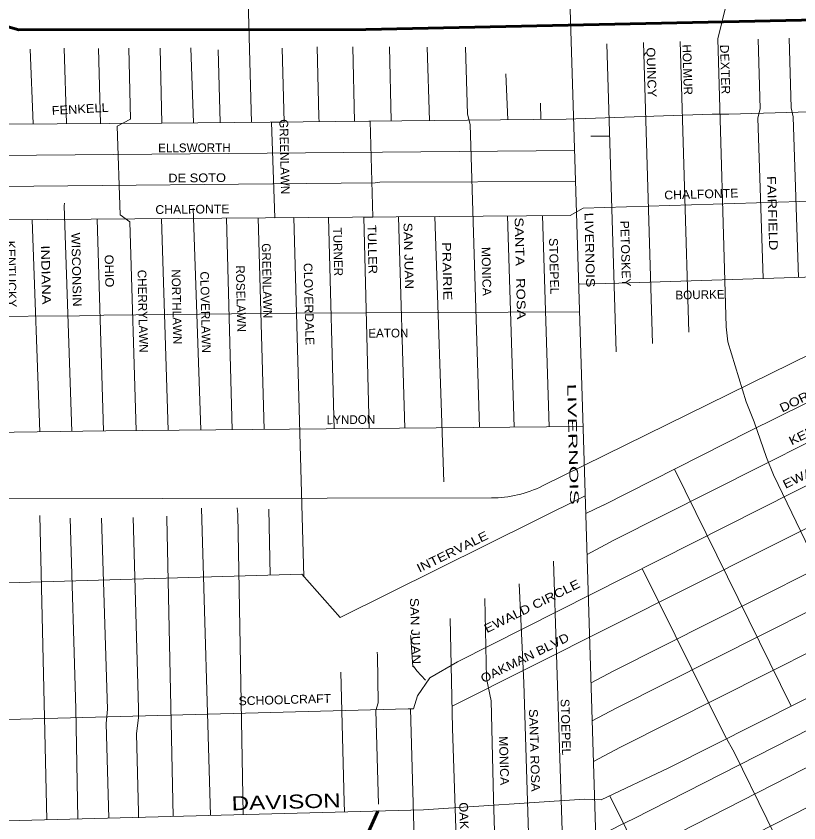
# Model space of a CAD drawing. Extents: x 34705 to 138605, y 34275 to 143551.
# Drawn here: x 69930 to 76666, y 119866 to 126812 of the extents above; entities that cross this region are included whole.
import ezdxf
from ezdxf.enums import TextEntityAlignment as Align

# ---------------------------------------------------------------- set-up
doc = ezdxf.new("R2010")
doc.units = 0
doc.header["$LTSCALE"] = 30
for name, color, linetype, lineweight in [('1', 7, 'Continuous', 13), ('11', 7, 'Continuous', 13), ('50', 7, 'Continuous', 13), ('51', 7, 'Continuous', 35)]:
    doc.layers.add(name, color=color, linetype=linetype, lineweight=lineweight)

msp = doc.modelspace()

# ---------------------------------------------------------------- linework, layer by layer
at = {"layer": '1'}
for p, q in [((76045.57, 126932.67), (75968.12, 126616.04)), ((75014.92, 126572.93), (75092.87, 123921.17)), ((75328.39, 126584.1), (75406.15, 123994.9)), ((75646.18, 126592.47), (75719.44, 124091.69)), ((70049.64, 126527.23), (70076.17, 125884.46)), ((70342.22, 126536.63), (70363.6, 125886.4)), ((70640.17, 126532.27), (70656.88, 125888.38)), ((71168.61, 126537.75), (71185.01, 125891.95)), ((71433.48, 126538.85), (71457.62, 125893.79)), ((71668.62, 126520.95), (71685.58, 125895.33)), ((73143.78, 126546.92), (73158.33, 125909.28)), ((73468.74, 126544.87), (73486.85, 125912.76)), ((74144.01, 126314.65), (74161.64, 125919.9)), ((74443.94, 126063.07), (74446.23, 125922.92)), ((72537.64, 125914.61), (72538.33, 125907.31)), ((74876.31, 125779.3), (75038.26, 125779.3)), ((69483.93, 125608.86), (74736.41, 125655.34)), ((71452.53, 125159.71), (71520, 123248.88)), ((70069.06, 125059.45), (70134, 123233.1)), ((70627.01, 125063.87), (70683.32, 123240.99)), ((71181.9, 125068.26), (71238.52, 123246.22)), ((71739.56, 125072.68), (71790.02, 123251.42)), ((72013.5, 125074.84), (72064.22, 123254)), ((72618.21, 125079.63), (72667.93, 123259.69)), ((73221.78, 125084.41), (73274.03, 123265.4)), ((73532.18, 125086.87), (73609.63, 122802.13)), ((74159.71, 125091.83), (74216.18, 123274.28)), ((74459.16, 125094.2), (74517.35, 123277.37)), ((75597.32, 122911.18), (76600.58, 120871.01)), ((71525.01, 122574.76), (71601.57, 119929.76)), ((72105.96, 122568.12), (72116.88, 121999.09)), ((74554.45, 122119.23), (74741.93, 116266.39)), ((73051.69, 119971.59), (73051.81, 119967.63))]:
    msp.add_line(p, q, dxfattribs=at)
for points in [[(74269.09, 141753.87), (74342.79, 139035.88), (74401.15, 136407.9), (74440.05, 135250.17), (74447.86, 135168.57), (74511.2, 133233.12), (74537.31, 132174.65), (74629.7, 129069.96), (74724.29, 126046.91), (75258.72, 108770.25), (75949.8, 107475.21), (75982.05, 107419.91), (76018.21, 107315.9)], [(71476.16, 141674.2), (71680.76, 133843.82), (71699.86, 133695.52), (71793.56, 131195.42), (71823.46, 129436.72), (71840.38, 128528.4), (71884.66, 128529.12), (71955.88, 125897.16)], [(75968.12, 126616.04), (76041.94, 124137.77), (76055.76, 124008.73), (76212.41, 123492.56), (76281.51, 123319.74), (76387.48, 123010.96), (76447.37, 122863.48), (76682.34, 122374.97), (76944.95, 121831.14), (78075.42, 119570.88)], [(76315.02, 126612.75), (76332.19, 126013.5), (76313.76, 125935.15), (76359.51, 124553.17)], [(76582.13, 126621.71), (76599.41, 126022.71), (76617.84, 125944.37), (76663.87, 124562.81)], [(70899.62, 126536.24), (70914.56, 125925.42), (70800.96, 125865.62), (70824.86, 125099.92), (70908.56, 125040.12), (70964.24, 123243.64)], [(72220.14, 126536.75), (72236.35, 125899.51), (72127.07, 125898.35), (72157.58, 125075.98), (72321.44, 125077.28), (72406.89, 121986.02)], [(72521.59, 126548.46), (72535.06, 125941.82), (72538.77, 125902.72)], [(72827.46, 126547.74), (72841, 125905.91), (72978.14, 125907.37), (73001.04, 125082.66), (72923.53, 125082.05), (72968.08, 123262.52)], [(73797.06, 126544.11), (73814.66, 125968.82), (73838.56, 125879.02), (73918.23, 123271.48)], [(71185.01, 125891.95), (72115.46, 125898.23), (74664.69, 125925.23), (75921.48, 125967.65), (76064.12, 125967.65), (76958.52, 125994.65), (77170.56, 126006.21), (78402.28, 126029.35), (80444.64, 126083.38)], [(82348.46, 126060.51), (80168.87, 124977.52), (78714.8, 124245.43), (77762.83, 122918.85), (73682.36, 120871.78)], [(69832.23, 125882.81), (71185.01, 125891.95)], [(69492.13, 125342.72), (73021.43, 125377.62), (73059.98, 125381.47), (74744.64, 125389.24)], [(55496.93, 125039.26), (55625.92, 124964.98), (55934.33, 124803.01), (56150.22, 124660.32), (56196.48, 124644.89), (58409.36, 124714.31), (60322.48, 124779.87), (61583.13, 124822.29), (61671.8, 124837.72), (64198.86, 124926.41), (64869.66, 124941.84), (66377.03, 124972.69), (66974.59, 124984.26), (69826.45, 125057.53), (74698.43, 125096.1), (74810.23, 125157.8), (77421.15, 125238.78)], [(70345.56, 125201.9), (70344.96, 125177.72), (70408.58, 123237)], [(74878.22, 121070.78), (75073.34, 121174.11), (78037.97, 122666.55), (79283.19, 123282.62), (80809.84, 124042.33), (82074.89, 124668.16)], [(74771.99, 124504.96), (75115.75, 124513.77), (77428.86, 124587.05)], [(74833.11, 122529.12), (74980.82, 122600.99), (74984.67, 122600.99), (76241.46, 123237.31), (78640.9, 124424.82)], [(74888.28, 120745.82), (75092.62, 120854.03), (78057.25, 122346.47), (78596.01, 122608.71), (82207.79, 124417.59)], [(68216.91, 124185.99), (68374.98, 124189.85), (68640.98, 124201.41), (68721.94, 124201.41), (69022.65, 124209.13), (69296.36, 124220.7), (69593.21, 124224.55), (70476.05, 124232.27), (70686.15, 124236.12), (72330.38, 124255.4), (74774.57, 124266.97)], [(74899.11, 120395.63), (75131.17, 120518.52), (78095.8, 122010.96), (79468.24, 122688.73), (81091.27, 123510.15), (81168.37, 123544.85), (81881.41, 123897.57), (81864.77, 123930.22), (82318.17, 124163.81), (82335.77, 124172.69)], [(74843.98, 122177.76), (75073.34, 122299.23), (78037.97, 123791.67), (78585.8, 124065.66)], [(82318.74, 123849.62), (82207.49, 123714.99), (81862.93, 123506.75), (80089.88, 122630.71), (75547.79, 120340.08), (74964.56, 120063.63), (74820.99, 120070.81), (73435.58, 119977.46), (69846.41, 119884.12), (65625.95, 119768.89)], [(46916.68, 119921.92), (52891.98, 120088.09), (53990.71, 120107.37), (55409.41, 120130.51), (55891.31, 120149.79), (57164.48, 120188.36), (57866.12, 120199.93), (58563.91, 120223.06), (59011.11, 120234.63), (60333.44, 120284.77), (62664.85, 120381.18), (62942.42, 120535.44), (65811.63, 120620.28), (69640.78, 120751.4), (73304.16, 120847.81), (73350.43, 120847.81), (73385.12, 120959.64), (73489.21, 121113.9), (73728.23, 121252.73), (77495.7, 123154.91), (77576.66, 123220.47), (77676.9, 123382.44), (77895.97, 123692.55)], [(74939.7, 119083.53), (75125.7, 119178.63), (75234.29, 119230.77), (77362.79, 120317.09), (77427.95, 120347.51), (77587.58, 120430.07), (77678.8, 120482.21), (79201.32, 121241.54), (79279.51, 121258.93), (79991.91, 121619.58), (80100.5, 121680.42), (81354.79, 122305.05), (81424.29, 122292.01), (82447.28, 122801.63), (82425.09, 122845.27), (83342.46, 123293.38)], [(58999.16, 122894.01), (59637.23, 122917.22), (59756.74, 122921.08), (60316.7, 122940.36), (61388.44, 122975.07), (62325.25, 123009.78), (63467.34, 123059.91), (64265.36, 123086.91), (64357.88, 123094.62), (66906.16, 123160.18), (67002.54, 123148.61), (68372.09, 123198.74), (68530.15, 123210.31), (70701.57, 123241.16), (74809.89, 123279.88)], [(65664.79, 121802.71), (66963.99, 121837.42), (67037.24, 121848.99), (72388.21, 122007.1), (72719.76, 121633.03), (74828.39, 122681.78)], [(71833.14, 122579.89), (71836.86, 122520.32), (71885.35, 119937.15)], [(74929.18, 119423.46), (75138.73, 119530.59), (75247.32, 119582.74), (77375.82, 120669.06), (77440.98, 120699.47), (79074.26, 121514.21), (79148.11, 121475.1), (79899.6, 121853.14), (79925.66, 121935.7), (81115.88, 122531)], [(70134.87, 122511.14), (70175.3, 120772.17), (70195.37, 119893.61)], [(70396.2, 122490.16), (70443.13, 120848), (70459.96, 119900.43)], [(70665.24, 122490.47), (70715.76, 120845.42), (70705.92, 120721.62), (70727.93, 119906.79)], [(70938.38, 122495.98), (70981.86, 120851.32), (70982.04, 120774.04), (70965.16, 120633.38), (70982.04, 119958.2), (70983.22, 119910.3)], [(71227.24, 122508.13), (71226.96, 122490.32), (71282.97, 119921.48)], [(75318.66, 122055.73), (76028.12, 120617.92), (76111.05, 120470.45), (76668.52, 119332.11), (76779.09, 119115.5), (77009.45, 118650.03), (77152.27, 118376.97), (77198.34, 118326.27), (79630.99, 113464.64)], [(74258.1, 121924.97), (74300.46, 121072.72), (74448.74, 116257.24)], [(73963.22, 121799.31), (73977.56, 121108.62), (74019.46, 120917.12), (74038.81, 120074.64), (74156.29, 116248.13), (74346.34, 116254.05), (74402.54, 113911.95), (74130.71, 114059.85), (74137.61, 113774.76)], [(74919.45, 119737.91), (75134.38, 119847.8), (75242.98, 119899.94), (77371.48, 120986.26), (77436.63, 121016.68), (78978.63, 121781.91)], [(73665.68, 121624.44), (73686.58, 120680.84), (73794.29, 117405.74), (73740.38, 117310.04), (73016.88, 116538.44), (72380.08, 116493.54), (72302.29, 116457.64), (72230.58, 116373.94), (72164.79, 116206.44), (71877.79, 115380.94), (71883.79, 115225.44), (71734.29, 114728.94), (71686.49, 114597.34), (71680.49, 114459.74), (71715.21, 113134.29), (71393.49, 112811.74), (71130.38, 112494.74), (70938.99, 112093.94), (69267.68, 110303.64)], [(73325.35, 121479.24), (73325.86, 121461.52), (73343.76, 121210.22), (73349.76, 121216.22), (73379.66, 121174.42), (73453.38, 121094.43)], [(73037.7, 121335.67), (73038.76, 121306.02), (73044.76, 120899.22), (73026.86, 120833.42), (73050.07, 120027.97)], [(72725.23, 121162.51), (72753.26, 120045.32), (72755.83, 119959.79)], [(73324.46, 120847.81), (73428.96, 117081.32), (73494.76, 117021.52), (73452.86, 116967.72), (73548.56, 116848.02), (73625.51, 114405.9)], [(75038.31, 120098.59), (76295.34, 117560.08), (78615.41, 112943.83)]]:
    msp.add_lwpolyline(points, dxfattribs=at)
at = {"layer": '50'}
msp.add_line((65680.66, 122650.65), (74020.14, 122663.94), dxfattribs=at)
msp.add_lwpolyline([(74460.14, 122766.73), (80880.53, 125926.78), (81087.82, 126043.54), (81230.41, 126153.09), (81491.96, 126306.55), (82079.69, 126598.83)], dxfattribs=at)
msp.add_arc((74018.55, 123663.94), 1000, 270.09134, 296.20599, dxfattribs=at)
at = {"layer": '51', "lineweight": 60}
for points in [[(69647.16, 126779.47), (69954.82, 126695.54), (72939.31, 126697.51), (77358.19, 126791.56), (78651.41, 126828.44), (78987.04, 126821.44), (79245.75, 126772.48), (79504.46, 126723.52), (79735.21, 126667.56), (80049.86, 126569.64), (80371.5, 126415.76), (80735.1, 126156.96), (81049.75, 125919.15), (81399.36, 125506.47), (81783.93, 125128.77), (82081.1, 124959.16), (82297.86, 124756.32), (82661.45, 124455.56), (83178.15, 123900.57), (83909.27, 122531.62)], [(71991.18, 119251.97), (72335.28, 119310.19), (72633.8, 119401.76), (72924.35, 119704.36), (73043.76, 119967.14)]]:
    msp.add_lwpolyline(points, dxfattribs=at)

# ---------------------------------------------------------------- texts
at = {"layer": '11'}
for s, rotation, p in [('HOLMUR', 271.708, (75670.52, 126349.97)), ('GREENLAWN', 271.302, (72202.87, 125600.86)), ('ELLSWORTH', 0.371, (71464.61, 125641.18)), ('TURNER', 271.409, (72662.3, 124781.57)), ('GREENLAWN', 271.302, (72051.69, 124532.47)), ('CHERRYLAWN', 271.302, (70983.34, 124270.78)), ('NORTHLAWN', 271.301, (71275.2, 124308.53)), ('ROSELAWN', 271.302, (71827.41, 124378.24)), ('CLOVERLAWN', 271.301, (71522.13, 124262.19)), ('BOURKE', 1.143, (75816.36, 124376.43)), ('EATON', 0.271, (73133.49, 124045.41)), ('LYNDON', 0.54, (72812.22, 123300.58))]:
    msp.add_text(s, height=75, rotation=rotation, dxfattribs=at).set_placement(p, align=Align.CENTER)
for s, height, rotation, width, p in [('DEXTER', 75, 271.711, 1.05, (75994.55, 126352.1)), ('QUINCY', 75, 271.707, 1.1, (75360.58, 126327.51)), ('FENKELL', 75, 3.162, 1.1, (70483.5, 125975.31)), ('DE SOTO', 75, 0.462, 1.1, (71488.37, 125382.19)), ('FAIRFIELD', 75, 271.709, 1.25, (76402.1, 125114.73)), ('CHALFONTE', 75, 1.662, 1.05, (75827.97, 125242.72)), ('CHALFONTE', 75, 0.58, 1.05, (71447.6, 125112.13)), ('LIVERNOIS', 75, 271.41, 1.2, (74828.98, 124797.86)), ('SANTA   ROSA', 75, 271.41, 1.25, (74231.04, 124639.86)), ('PETOSKEY', 75, 271.707, 1.05, (75137.22, 124766.19)), ('TULLER', 75, 271.41, 1.1, (72958.46, 124802.56)), ('SAN JUAN', 75, 271.408, 1.15, (73270.66, 124746.77)), ('WISCONSIN', 75, 271.302, 1.1, (70412.26, 124629.16)), ('STOEPEL', 75, 271.409, 1.05, (74522.28, 124657.77)), ('KENTUCKY', 75, 271.302, 1.05, (69853.02, 124590.76)), ('INDIANA', 75, 271.3, 1.25, (70149.08, 124582.77)), ('PRAIRIE', 75, 271.408, 1.25, (73602.02, 124615.29)), ('OHIO', 75, 271.3, 1.1, (70695.12, 124617.19)), ('MONICA', 75, 271.409, 1.05, (73940.26, 124613.85)), ('CLOVERDALE', 75, 271.411, 1.05, (72412.63, 124332.08)), ('LIVERNOIS', 75, 271.41, 1.95, (74685.21, 123125.05)), ('DORIS', 75, 26.17, 1.2, (76694.22, 123482.58)), ('KENDALL', 75, 26.228, 1.15, (76840.27, 123231.76)), ('EWALD CIRCLE', 75, 26.23, 1.2, (76956.05, 122940.76)), ('INTERVALE', 75, 26.241, 1.2, (73700.65, 122166.77)), ('EWALD CIRCLE', 75, 26.241, 1.2, (74385.79, 121698.5)), ('SAN JUAN', 75, 271.796, 1.15, (73328.4, 121516.79)), ('OAKMAN BLVD', 75, 26.241, 1.15, (74324.45, 121253)), ('SCHOOLCRAFT', 75, 1.619, 1.05, (72243.21, 120889.28)), ('STOEPEL', 75, 271.683, 1.05, (74622.68, 120689.65)), ('SANTA ROSA', 75, 271.68, 1.1, (74353.98, 120490.22)), ('MONICA', 75, 271.682, 1.05, (74091.82, 120400.6)), ('DAVISON', 120, 1.62, 1.3, (72255.27, 119987.23)), ('OAKMAN BLVD', 75, 271.68, 1.1, (73754.37, 119643.91))]:
    msp.add_text(s, height=height, rotation=rotation, dxfattribs=dict(at, width=width)).set_placement(p, align=Align.CENTER)

doc.saveas('drawing.dxf')
